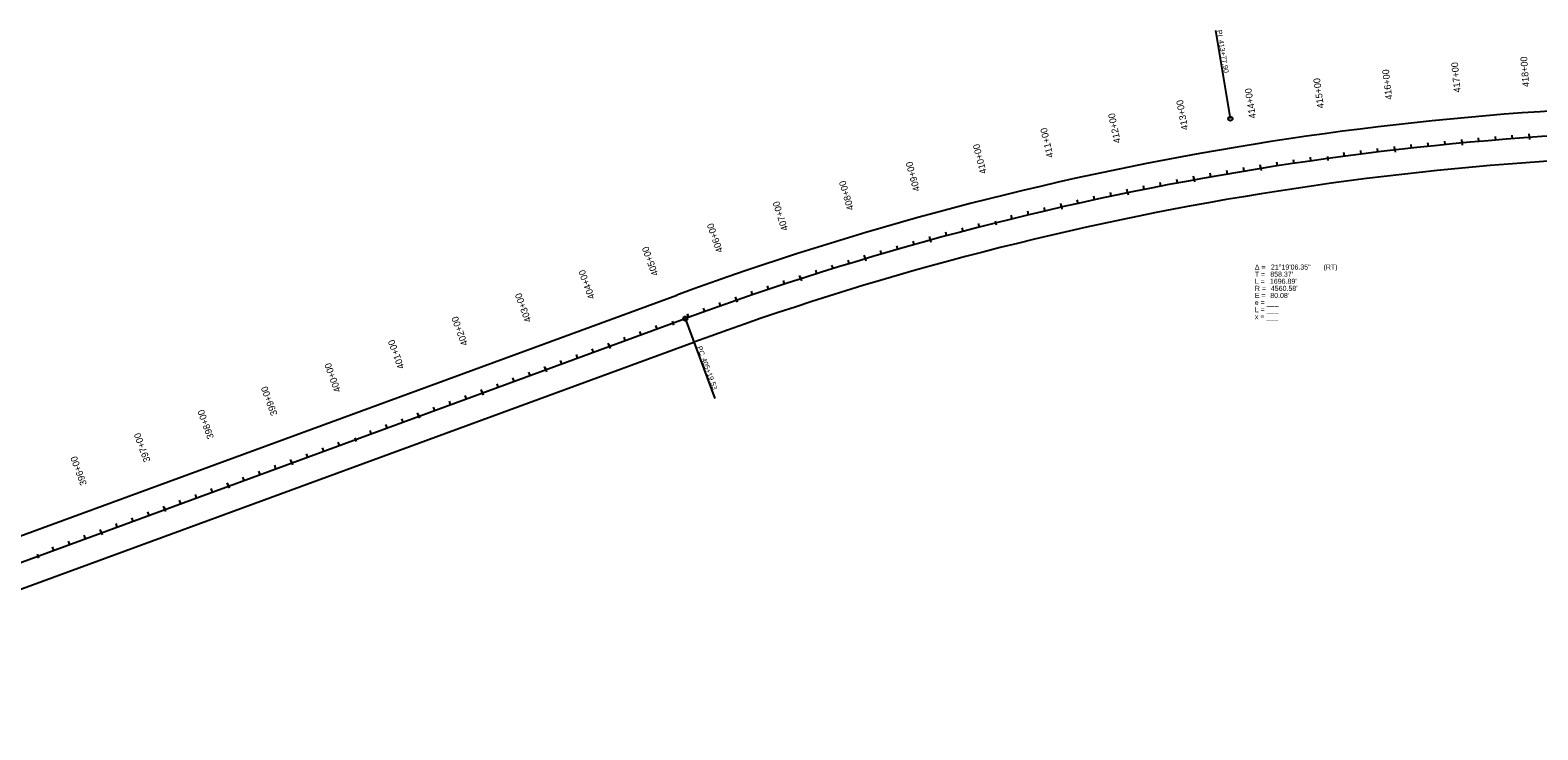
# Model space of a CAD drawing. Extents: x 21369364 to 21378321, y 8396964 to 8399934.
# Drawn here: x 21373853 to 21376081, y 8397734 to 8398769 of the extents above; entities that cross this region are included whole.
import ezdxf

# ---------------------------------------------------------------- set-up
doc = ezdxf.new("R2010")
doc.units = 0
for name, color, linetype in [('Alignment', 7, 'Continuous'), ('Level 1', 7, 'Continuous'), ('Level 60', 7, 'Continuous'), ('TextNonPlot', 7, 'Continuous')]:
    doc.layers.add(name, color=color, linetype=linetype)

msp = doc.modelspace()

# ---------------------------------------------------------------- linework, layer by layer
at = {"layer": 'Alignment'}
msp.add_line((21373258.8, 8397768.9), (21374821.1, 8398342.5), dxfattribs=at)
msp.add_arc((21376392.9, 8394061.3), 4560.6, 88.8415, 110.16, dxfattribs=at)
at = {"layer": 'Level 1'}
for p, q in [((21375626.9, 8398638.3), (21375605.1, 8398768.5)), ((21375605.1, 8398768.5), (21375605.1, 8398768.5)), ((21374821.1, 8398342.5), (21374864.5, 8398224.2)), ((21374864.5, 8398224.2), (21374864.5, 8398224.2))]:
    msp.add_line(p, q, dxfattribs=at)
for centre in [(21375626.9, 8398638.3), (21374821.1, 8398342.5)]:
    msp.add_circle(centre, 3.12, dxfattribs=at)
at = {"layer": 'Level 60'}
for p, q in [((21375944.4, 8398599.8), (21375943.8, 8398605.2)), ((21375969, 8398605.2), (21375969.5, 8398599.1)), ((21375994.2, 8398604.4), (21375993.7, 8398609.9)), ((21376019.1, 8398606.5), (21376018.6, 8398612)), ((21376044, 8398608.5), (21376043.6, 8398614)), ((21376068.7, 8398613.4), (21376069.1, 8398607.3)), ((21375795.4, 8398582.6), (21375794.7, 8398588)), ((21375820.2, 8398585.8), (21375819.5, 8398591.2)), ((21375845, 8398588.9), (21375844.3, 8398594.3)), ((21375869.5, 8398594.8), (21375870.2, 8398588.8)), ((21375894.6, 8398594.6), (21375894.1, 8398600)), ((21375919.5, 8398597.3), (21375918.9, 8398602.7)), ((21375622.4, 8398556.3), (21375621.4, 8398561.7)), ((21375647, 8398560.5), (21375646.1, 8398565.9)), ((21375671.2, 8398567.5), (21375672.2, 8398561.5)), ((21375696.4, 8398568.4), (21375695.6, 8398573.8)), ((21375721.1, 8398572.1), (21375720.3, 8398577.5)), ((21375745.8, 8398575.8), (21375745.1, 8398581.2)), ((21375770.2, 8398582.3), (21375771, 8398576.2)), ((21375499.5, 8398533.5), (21375498.4, 8398538.9)), ((21375524, 8398538.4), (21375523, 8398543.7)), ((21375548.6, 8398543.1), (21375547.5, 8398548.4)), ((21375572.6, 8398550.6), (21375573.7, 8398544.6)), ((21375597.7, 8398552), (21375596.8, 8398557.4)), ((21375401.6, 8398512.9), (21375400.4, 8398518.2)), ((21375426, 8398518.2), (21375424.9, 8398523.6)), ((21375450.5, 8398523.5), (21375449.4, 8398528.8)), ((21375474.3, 8398531.6), (21375475.6, 8398525.6)), ((21375304.3, 8398490.1), (21375303, 8398495.4)), ((21375328.6, 8398496), (21375327.3, 8398501.3)), ((21375352.9, 8398501.7), (21375351.6, 8398507)), ((21375376.6, 8398510.3), (21375377.9, 8398504.4)), ((21375231.6, 8398471.6), (21375230.2, 8398476.8)), ((21375255.8, 8398477.9), (21375254.4, 8398483.2)), ((21375279.3, 8398487), (21375280.7, 8398481.1)), ((21375135.2, 8398445), (21375133.7, 8398450.3)), ((21375159.2, 8398451.9), (21375157.7, 8398457.1)), ((21375182.5, 8398461.5), (21375184.1, 8398455.6)), ((21375207.4, 8398465.1), (21375206, 8398470.4)), ((21375063.2, 8398423.8), (21375061.7, 8398429)), ((21375086.3, 8398433.9), (21375088.1, 8398428.1)), ((21375111.2, 8398438.1), (21375109.6, 8398443.3)), ((21375015.5, 8398408.9), (21375013.9, 8398414.1)), ((21375039.4, 8398416.4), (21375037.7, 8398421.6)), ((21374920.5, 8398377.7), (21374918.7, 8398382.9)), ((21374944.2, 8398385.7), (21374942.5, 8398390.9)), ((21374967.9, 8398393.6), (21374966.2, 8398398.8)), ((21374990.7, 8398404.2), (21374992.6, 8398398.4)), ((21374873.3, 8398361.3), (21374871.5, 8398366.4)), ((21374895.9, 8398372.4), (21374897.9, 8398366.7)), ((21374801.7, 8398338.6), (21374803.8, 8398332.9)), ((21374826.2, 8398344.4), (21374824.3, 8398349.5)), ((21374849.7, 8398352.9), (21374847.9, 8398358)), ((21374755.8, 8398318.5), (21374753.9, 8398323.6)), ((21374779.3, 8398327.1), (21374777.4, 8398332.3)), ((21374685.4, 8398292.7), (21374683.5, 8398297.8)), ((21374707.8, 8398304.2), (21374709.9, 8398298.4)), ((21374732.3, 8398309.9), (21374730.5, 8398315)), ((21374638.5, 8398275.4), (21374636.6, 8398280.6)), ((21374661.9, 8398284.1), (21374660.1, 8398289.2)), ((21374568.1, 8398249.6), (21374566.2, 8398254.7)), ((21374591.5, 8398258.2), (21374589.7, 8398263.3)), ((21374614, 8398269.7), (21374616.1, 8398264)), ((21374497.7, 8398223.7), (21374495.8, 8398228.9)), ((21374520.1, 8398235.2), (21374522.2, 8398229.5)), ((21374544.6, 8398241), (21374542.7, 8398246.1)), ((21374450.7, 8398206.5), (21374448.8, 8398211.6)), ((21374474.2, 8398215.1), (21374472.3, 8398220.3)), ((21374380.3, 8398180.7), (21374378.4, 8398185.8)), ((21374403.8, 8398189.3), (21374401.9, 8398194.4)), ((21374426.2, 8398200.8), (21374428.3, 8398195)), ((21374309.9, 8398154.8), (21374308, 8398159.9)), ((21374332.3, 8398166.3), (21374334.4, 8398160.6)), ((21374356.9, 8398172), (21374355, 8398177.2)), ((21374263, 8398137.6), (21374261.1, 8398142.7)), ((21374286.5, 8398146.2), (21374284.6, 8398151.3)), ((21374192.6, 8398111.7), (21374190.7, 8398116.9)), ((21374216, 8398120.3), (21374214.2, 8398125.5)), ((21374238.5, 8398131.8), (21374240.6, 8398126.1)), ((21374144.6, 8398097.4), (21374146.7, 8398091.6)), ((21374169.1, 8398103.1), (21374167.2, 8398108.2)), ((21374075.2, 8398068.7), (21374073.4, 8398073.8)), ((21374098.7, 8398077.3), (21374096.8, 8398082.4)), ((21374122.2, 8398085.9), (21374120.3, 8398091)), ((21374004.8, 8398042.8), (21374002.9, 8398047.9)), ((21374028.3, 8398051.4), (21374026.4, 8398056.5)), ((21374050.7, 8398062.9), (21374052.8, 8398057.2)), ((21373956.8, 8398028.4), (21373958.9, 8398022.7)), ((21373981.4, 8398034.2), (21373979.5, 8398039.3)), ((21373887.5, 8397999.7), (21373885.6, 8398004.9)), ((21373911, 8398008.3), (21373909.1, 8398013.5)), ((21373934.4, 8398017), (21373932.5, 8398022.1)), ((21373863, 8397994), (21373865.1, 8397988.2))]:
    msp.add_line(p, q, dxfattribs=at)
at = {"layer": 'TextNonPlot'}
for p, q in [((21375969.3, 8398602.2), (21375968.8, 8398607.6)), ((21376068.9, 8398610.4), (21376068.5, 8398615.8)), ((21375869.8, 8398591.8), (21375869.2, 8398597.2)), ((21375671.7, 8398564.5), (21375670.8, 8398569.9)), ((21375770.2, 8398582.3), (21375771, 8398576.2)), ((21375573.1, 8398547.6), (21375572.1, 8398553)), ((21375475, 8398528.6), (21375473.9, 8398533.9)), ((21375377.2, 8398507.4), (21375376, 8398512.7)), ((21375279.3, 8398487), (21375280.7, 8398481.1)), ((21375183.3, 8398458.6), (21375181.9, 8398463.8)), ((21375087.2, 8398431), (21375085.6, 8398436.2)), ((21374991.7, 8398401.3), (21374990, 8398406.5)), ((21373246.1, 8397803.6), (21374808.3, 8398377.2)), ((21374896.9, 8398369.5), (21374895.1, 8398374.7)), ((21374801.7, 8398338.6), (21374803.8, 8398332.9)), ((21373271.6, 8397734.2), (21374833.8, 8398307.8)), ((21374708.9, 8398301.3), (21374707, 8398306.4)), ((21374615, 8398266.8), (21374613.1, 8398271.9)), ((21374521.1, 8398232.4), (21374519.3, 8398237.5)), ((21374427.3, 8398197.9), (21374425.4, 8398203)), ((21374332.3, 8398166.3), (21374334.4, 8398160.6)), ((21374239.5, 8398129), (21374237.6, 8398134.1)), ((21374145.6, 8398094.5), (21374143.8, 8398099.6)), ((21374051.8, 8398060), (21374049.9, 8398065.2)), ((21373957.9, 8398025.6), (21373956, 8398030.7)), ((21373863, 8397994), (21373865.1, 8397988.2))]:
    msp.add_line(p, q, dxfattribs=at)
for radius in [4597.6, 4523.6]:
    msp.add_arc((21376392.9, 8394061.3), radius, 88.8415, 110.16, dxfattribs=at)

# ---------------------------------------------------------------- texts
at = {"layer": 'Level 1'}
for s, rotation, p in [('PI ', 279.5007, (21375606.7, 8398768.8)), ('413+77.90', 279.5007, (21375609.2, 8398754)), ('PC', 290.16, (21374838.3, 8398300.3)), ('405+19.53', 290.16, (21374844.8, 8398282.8))]:
    msp.add_text(s, height=7.5, rotation=rotation, dxfattribs=at).set_placement(p)
for s, p in [('T = ', (21375663, 8398404.5)), ('Δ = ', (21375663, 8398415)), ("858.37'", (21375685.8, 8398404.5)), ('21°19\'06.35"', (21375686.7, 8398415)), (' (RT)', (21375761.6, 8398415)), ('L = ', (21375663, 8398394)), ('R = ', (21375663, 8398383.5)), ("1696.89'", (21375685.3, 8398394)), ("4560.58'", (21375686.7, 8398383.5)), ('e = ___ ', (21375663, 8398362.5)), ('E = ', (21375663, 8398373)), ("80.08'", (21375685.8, 8398373)), ('x = ___', (21375663, 8398341.5)), ('L = ___', (21375663, 8398352))]:
    msp.add_text(s, height=7.5, dxfattribs=at).set_placement(p)
at = {"layer": 'Level 60'}
for s, rotation, p in [('417+00', 95.3295, (21375967.3, 8398677.3)), ('418+00', 94.0731, (21376068.6, 8398685.5)), ('415+00', 97.8421, (21375765.3, 8398654.2)), ('416+00', 96.5858, (21375866.2, 8398666.9)), ('414+00', 99.0984, (21375664.8, 8398639.4)), ('413+00', 100.3548, (21375564.6, 8398622.3)), ('412+00', 101.6111, (21375464.8, 8398603)), ('411+00', 102.8674, (21375365.4, 8398581.6)), ('410+00', 104.1237, (21375266.6, 8398558)), ('409+00', 105.3801, (21375168.2, 8398532.2)), ('408+00', 106.6364, (21375070.5, 8398504.3)), ('407+00', 107.8927, (21374973.4, 8398474.2)), ('406+00', 109.1491, (21374877, 8398442)), ('405+00', 110.16, (21374781.6, 8398407.9)), ('404+00', 110.16, (21374687.7, 8398373.4)), ('403+00', 110.16, (21374593.9, 8398339)), ('402+00', 110.16, (21374500, 8398304.5)), ('401+00', 110.16, (21374406.1, 8398270)), ('400+00', 110.16, (21374312.2, 8398235.6)), ('399+00', 110.16, (21374218.4, 8398201.1)), ('398+00', 110.16, (21374124.5, 8398166.6)), ('397+00', 110.16, (21374030.6, 8398132.2)), ('396+00', 110.16, (21373936.7, 8398097.7))]:
    msp.add_text(s, height=10.02, rotation=rotation, dxfattribs=at).set_placement(p)
at = {"layer": 'TextNonPlot'}
for s, rotation, p in [('415+00', 97.8421, (21375765.3, 8398654.2)), ('410+00', 104.1237, (21375266.6, 8398558)), ('405+00', 110.16, (21374781.6, 8398407.9)), ('400+00', 110.16, (21374312.2, 8398235.6))]:
    msp.add_text(s, height=10.02, rotation=rotation, dxfattribs=at).set_placement(p)

doc.saveas('drawing.dxf')
